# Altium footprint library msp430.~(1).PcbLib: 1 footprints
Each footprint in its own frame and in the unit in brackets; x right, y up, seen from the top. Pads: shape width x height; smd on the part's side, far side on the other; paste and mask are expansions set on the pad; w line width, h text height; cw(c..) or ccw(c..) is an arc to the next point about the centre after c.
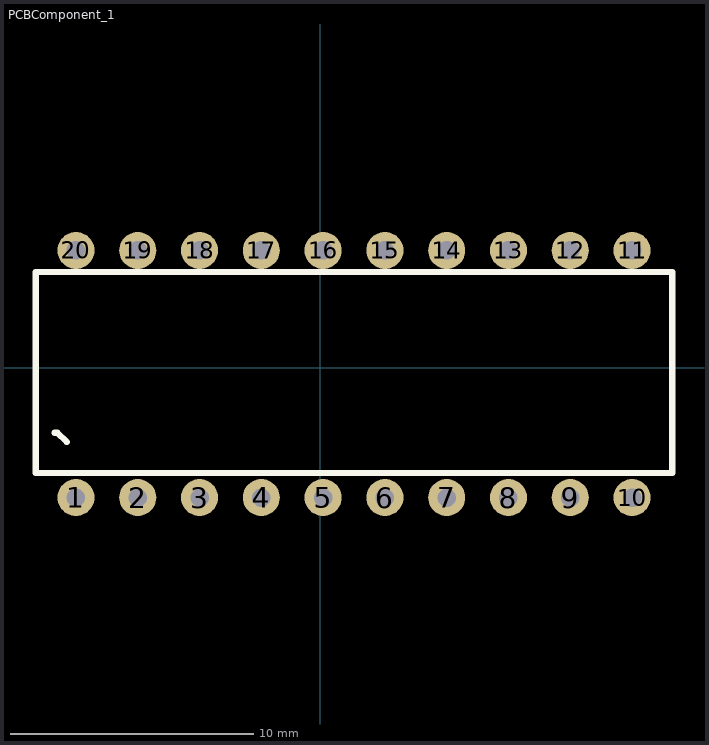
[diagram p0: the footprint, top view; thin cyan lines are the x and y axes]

## PCBComponent_1 [mil]
pads (20):
  round 60 hole 30: 1(-395,-210) 2(-295,-210) 3(-195,-210) 4(-95,-210) 5(5,-210) 6(105,-210) 7(205,-210) 8(305,-210) 9(405,-210) 10(505,-210) 11(505,190) 12(405,190) 13(305,190) 14(205,190) 15(105,190) 16(5,190) 17(-95,190) 18(-195,190) 19(-295,190) 20(-395,190)
Top Overlay:
  lines w10: -430,-105 -425,-105 -410,-120 ; -460,-170 -460,155 570,155 570,-170 -460,-170
3D body: height 325, standoff 0, extent -460,-170 565,155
